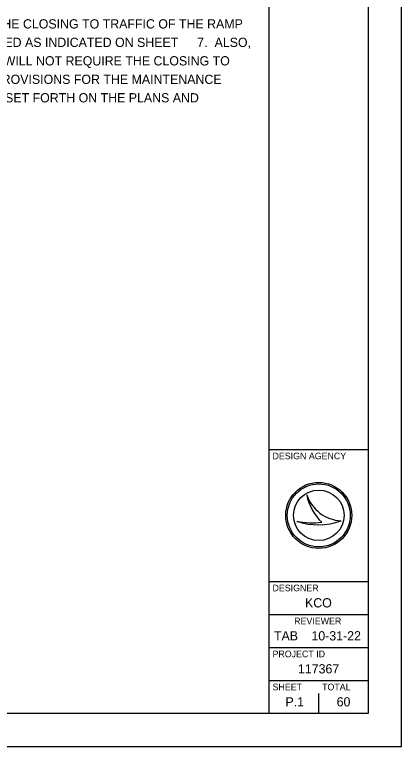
# Model space of a CAD drawing. Extents: x 0 to 64.8, y -5 to 22.
# Drawn here: x 28.15 to 34, y 0 to 11.09 of the extents above; entities that cross this region are included whole.
import ezdxf

# ---------------------------------------------------------------- set-up
doc = ezdxf.new("R2010")
doc.units = 0
for name, color, linetype in [('SH_Border', 7, 'Continuous'), ('SH_Cut_Line', 7, 'Continuous'), ('SH_Data', 7, 'Continuous'), ('SH_Text', 7, 'Continuous')]:
    doc.layers.add(name, color=color, linetype=linetype)

msp = doc.modelspace()

# ---------------------------------------------------------------- linework, layer by layer
at = {"layer": 'SH_Border'}
for p, q in [((32, 0.5), (32, 21.5)), ((32, 4.5), (33.5, 4.5)), ((32, 2.5), (33.5, 2.5)), ((32, 2), (33.5, 2)), ((32, 1.5), (33.5, 1.5)), ((32, 1), (33.5, 1))]:
    msp.add_line(p, q, dxfattribs=at)
msp.add_lwpolyline([(1.5, 21.5), (33.5, 21.5), (33.5, 0.5), (1.5, 0.5)], close=True, dxfattribs=at)
at = {"layer": 'SH_Cut_Line'}
msp.add_lwpolyline([(0, 0), (34, 0), (34, 22), (0, 22)], close=True, dxfattribs=at)
at = {"layer": 'SH_Data'}
for p, q in [((32.567, 3.81), (32.567, 3.81)), ((32.75, 3.5), (32.75, 3.5)), ((32.417, 3.41), (32.417, 3.41)), ((33.087, 3.419), (33.087, 3.419)), ((32.75, 0.5), (32.75, 0.8)), ((32.375, 0.675), (32.375, 0.675))]:
    msp.add_line(p, q, dxfattribs=at)
for radius in [0.5, 0.477, 0.477, 0.382]:
    msp.add_circle((32.75, 3.5), radius, dxfattribs=at)
for centre, radius, start, end in [((33.116, 3.998), 0.58, 198.9257, 198.9319), ((33.347, 3.97), 0.796, 191.6379, 191.6421), ((33.116, 3.998), 0.58, 198.9319, 267.1657), ((33.347, 3.97), 0.796, 191.6421, 226.0947), ((32.739, 4.37), 1.013, 251.4576, 290.0832), ((32.648, 4.654), 1.266, 259.4964, 259.4995), ((32.739, 4.37), 1.013, 251.4527, 251.4576), ((32.648, 4.654), 1.266, 259.4995, 276.6672)]:
    msp.add_arc(centre, radius, start, end, dxfattribs=at)

# ---------------------------------------------------------------- texts
for s, height, p in [('DESIGN AGENCY', 0.1, (32.05, 4.35)), ('DESIGNER', 0.1, (32.05, 2.35)), ('KCO', 0.14, (32.542, 2.105)), ('REVIEWER', 0.1, (32.378, 1.85)), ('TAB', 0.14, (32.072, 1.605)), ('10-31-22', 0.14, (32.639, 1.605)), ('PROJECT ID', 0.1, (32.05, 1.35)), ('117367', 0.14, (32.435, 1.105)), ('SHEET', 0.1, (32.05, 0.85)), ('TOTAL', 0.1, (32.8, 0.85)), ('P.1', 0.14, (32.246, 0.605)), ('60', 0.14, (33.021, 0.605))]:
    msp.add_text(s, height=height, dxfattribs=at).set_placement(p)
at = {"layer": 'SH_Text'}
for s, p in [('THIS IMPROVEMENT WILL REQUIRE THE CLOSING TO TRAFFIC OF THE RAMP ', (24.528, 10.877)), ('AND THAT DETOURS WILL BE PROVIDED AS INDICATED ON SHEET ', (24.528, 10.597)), ('7', (30.908, 10.597)), ('.  ALSO, ', (31.017, 10.597)), ('THE MAKING OF THIS IMPROVEMENT WILL NOT REQUIRE THE CLOSING TO ', (24.528, 10.317)), ('TRAFFIC OF US 24 AND US 127 AND PROVISIONS FOR THE MAINTENANCE ', (24.528, 10.037)), ('AND SAFETY OF TRAFFIC WILL BE AS SET FORTH ON THE PLANS AND ', (24.528, 9.757))]:
    msp.add_text(s, height=0.14, dxfattribs=at).set_placement(p)

doc.saveas('drawing.dxf')
